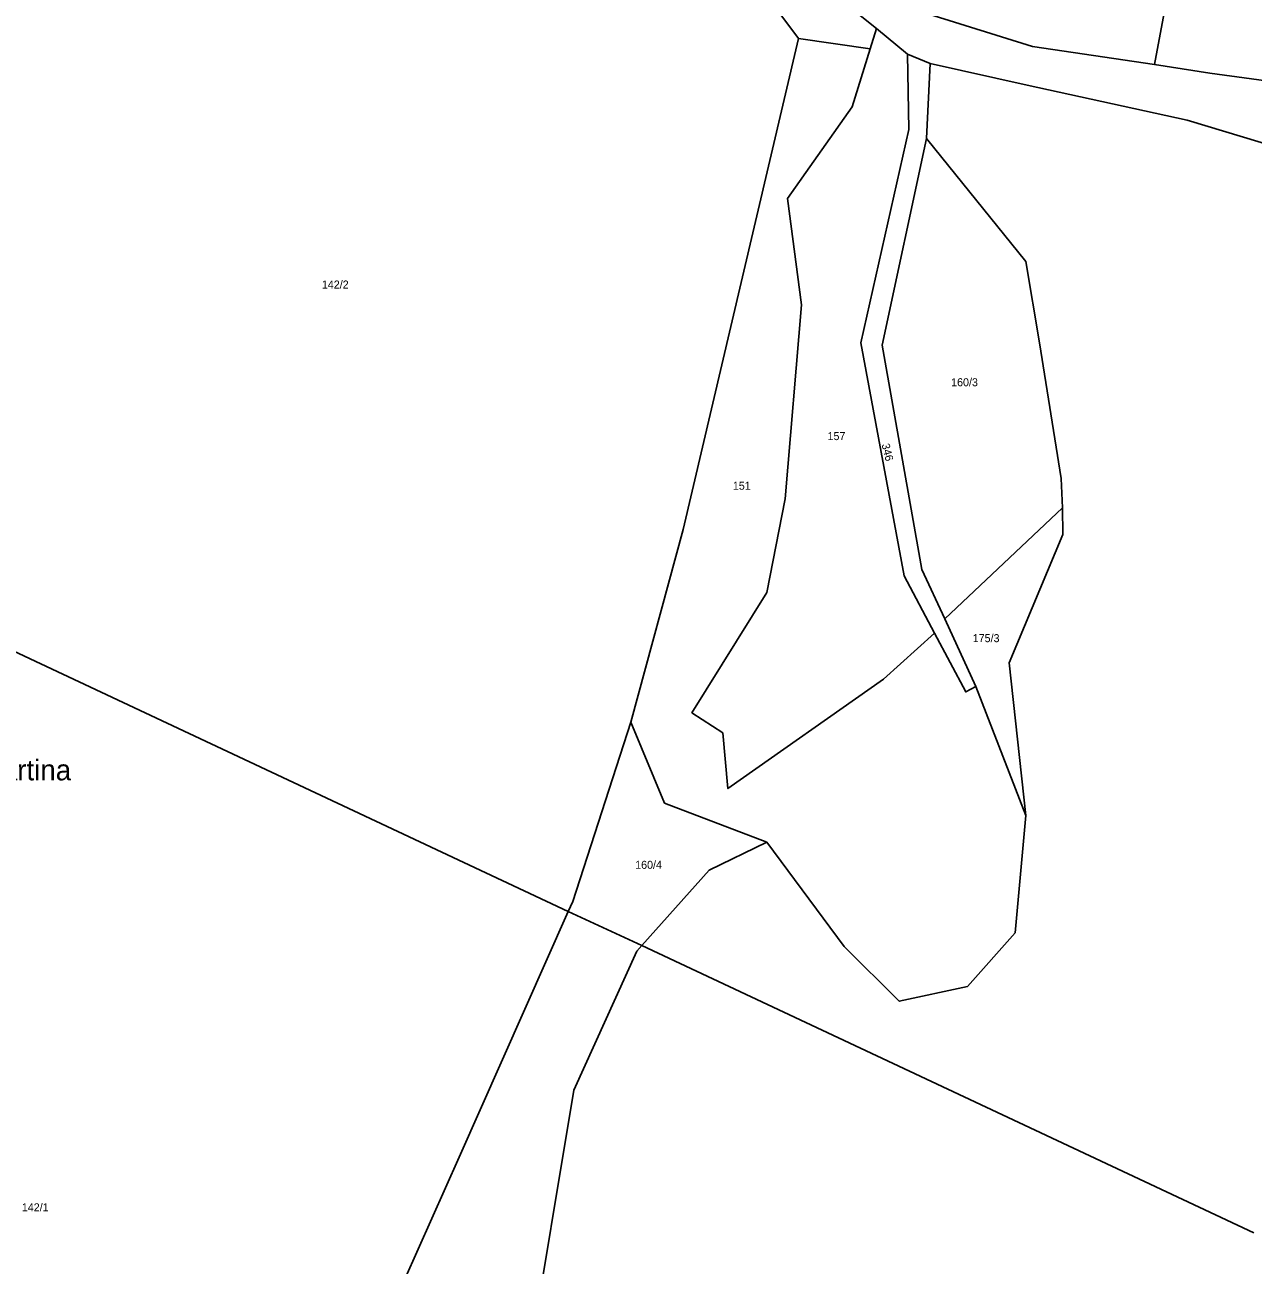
# Model space of a CAD drawing. Extents: x -880531 to -877616, y -1023932 to -1021350.
# Drawn here: x -878781.4 to -878520.6, y -1022969 to -1022705.7 of the extents above; entities that cross this region are included whole.
import ezdxf

# ---------------------------------------------------------------- set-up
doc = ezdxf.new("R2010")
doc.units = 0
for name, color, linetype in [('Hranice parcel', 7, 'Continuous'), ('Parcelní čísla', 7, 'Continuous'), ('Pop  PČ popisy', 7, 'Continuous'), ('Vnitřní kresba', 7, 'Continuous')]:
    doc.layers.add(name, color=color, linetype=linetype)

msp = doc.modelspace()

# ---------------------------------------------------------------- linework, layer by layer
at = {"layer": 'Hranice parcel'}
for p, q in [((-878541.54, -1022714.07), (-878526.53, -1022633.22)), ((-878600.6, -1022706.46), (-878605.47, -1022702.56)), ((-878594, -1022711.88), (-878600.6, -1022706.46)), ((-878589.15, -1022713.89), (-878594, -1022711.88)), ((-878589.15, -1022713.89), (-878589.96, -1022729.78)), ((-878586.09, -1022831.8), (-878561.06, -1022808.24)), ((-878666.02, -1022893.96), (-878818.61, -1022822.28)), ((-878586.09, -1022831.8), (-878579.47, -1022846.16)), ((-878568.84, -1022873.53), (-878579.47, -1022846.16)), ((-878650.42, -1022901.16), (-878666.02, -1022893.96)), ((-878520.42, -1022962.14), (-878650.42, -1022901.16))]:
    msp.add_line(p, q, dxfattribs=at)
for points in [[(-878607.12, -1022686.24), (-878589.44, -1022703.39), (-878567.47, -1022710.29), (-878541.54, -1022714.07)], [(-878652.74, -1022853.75), (-878641.61, -1022812.8), (-878629.32, -1022760.4), (-878617.11, -1022708.59), (-878628.11, -1022693.81)], [(-878588.23, -1022834.82), (-878599.1, -1022844.62), (-878632.14, -1022867.85), (-878633.2, -1022856.01), (-878639.78, -1022851.75), (-878623.85, -1022826.19), (-878619.98, -1022806.32), (-878616.49, -1022765.11), (-878619.5, -1022742.51), (-878605.77, -1022723.09), (-878601.93, -1022710.75), (-878600.6, -1022706.46)], [(-878588.23, -1022834.82), (-878594.71, -1022822.64), (-878603.91, -1022773.16), (-878593.73, -1022727.86), (-878594, -1022711.88)], [(-878428.81, -1022765.67), (-878444.18, -1022760.32), (-878469.54, -1022751.18), (-878503.13, -1022735.42), (-878534.57, -1022725.92), (-878568.59, -1022718.45), (-878589.15, -1022713.89)], [(-878541.54, -1022714.07), (-878529.74, -1022715.93), (-878513.6, -1022718.13)], [(-878589.96, -1022729.78), (-878599.37, -1022773.7), (-878590.92, -1022821.3), (-878586.09, -1022831.8)], [(-878561.06, -1022808.24), (-878561.37, -1022801.97), (-878565.95, -1022773.17), (-878568.84, -1022755.94), (-878589.96, -1022729.78)], [(-878568.84, -1022873.53), (-878572.36, -1022841.14), (-878560.96, -1022813.88), (-878561.06, -1022808.24)], [(-878579.47, -1022846.16), (-878581.62, -1022847.3), (-878588.23, -1022834.82)], [(-878666.02, -1022893.96), (-878665.07, -1022891.82), (-878652.74, -1022853.75)], [(-878652.74, -1022853.75), (-878645.58, -1022870.92), (-878623.84, -1022879.21)], [(-878623.84, -1022879.21), (-878607.43, -1022901.35), (-878595.72, -1022912.99), (-878581.26, -1022909.88), (-878571.13, -1022898.49), (-878568.84, -1022873.53)], [(-878650.42, -1022901.16), (-878636.11, -1022885.19), (-878623.84, -1022879.21)], [(-878763.61, -1023067.45), (-878725.84, -1023021.73), (-878709.52, -1022991.72), (-878689.19, -1022946.1), (-878666.02, -1022893.96)], [(-878663.89, -1023075.15), (-878666.12, -1023056.96), (-878663.68, -1023028.99), (-878674.54, -1022990.2), (-878664.83, -1022931.9), (-878651.48, -1022902.34), (-878650.42, -1022901.16)]]:
    msp.add_lwpolyline(points, dxfattribs=at)
at = {"layer": 'Vnitřní kresba'}
msp.add_line((-878617.11, -1022708.59), (-878601.93, -1022710.75), dxfattribs=at)

# ---------------------------------------------------------------- texts
at = {"layer": 'Parcelní čísla'}
for s, p in [('142/2', (-878718.36, -1022761.66)), ('160/3', (-878584.72, -1022782.41)), ('157', (-878610.97, -1022793.84)), ('151', (-878631.08, -1022804.38)), ('175/3', (-878580.13, -1022836.75)), ('160/4', (-878651.82, -1022884.88)), ('142/1', (-878782.08, -1022957.61))]:
    msp.add_text(s, height=1.7, dxfattribs=at).set_placement(p)
msp.add_text('346', height=1.7, rotation=284, dxfattribs=at).set_placement((-878599.494, -1022794.775))
at = {"layer": 'Pop  PČ popisy'}
msp.add_text('U Martina', height=4.4, dxfattribs=at).set_placement((-878797.11, -1022866.09))

doc.saveas('drawing.dxf')
